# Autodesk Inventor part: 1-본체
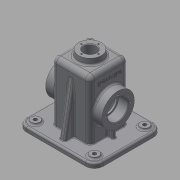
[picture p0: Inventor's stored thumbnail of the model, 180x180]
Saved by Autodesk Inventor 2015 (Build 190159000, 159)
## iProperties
Created: 2016-06
Part Number: 1-본체
Material: 일반
Document SubType Name: Modeling
Designer: aa
Density: 1 g/cm^3
Appearance: 기본값
Author: aa
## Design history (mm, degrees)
sketch "스케치1"
  geometry: L1 (65, -57.5)-(-65, -57.5); L2 (-65, -57.5)-(-65, 57.5); L3 (-65, 57.5)-(65, 57.5); L4 (65, 57.5)-(65, -57.5); L5 (65, -57.5)-(-65, 57.5); L6 (-65, -57.5)-(65, 57.5); 1 further point
  constraints: 12 end point, 2 midpoint, 2 parallel, 1 horizontal, 1 perpendicular
  dimensions: "d0" = 130 distance between parallel lines of L4 L2; "d1" = 115 distance between parallel lines of L1 L3
extrude "돌출1" new body sketch "스케치1" distance "d2" = 10; taper "d3" = 0 deg
sketch "스케치2"
  geometry: L1 (32.5, -32.5)-(-32.5, -32.5); L2 (-32.5, -32.5)-(-32.5, 32.5); L3 (-32.5, 32.5)-(32.5, 32.5); L4 (32.5, 32.5)-(32.5, -32.5); L5 (32.5, -32.5)-(-32.5, 32.5); L6 (-32.5, -32.5)-(32.5, 32.5); 1 further point
  constraints: 12 end point, 2 midpoint, 2 parallel, 1 horizontal, 1 perpendicular
  dimensions: "d4" = 65 distance between parallel lines of L4 L2; "d5" = 65 distance of L3.end L1.start (= d4)
extrude "돌출2" join sketch "스케치2" distance "d6" = 100; taper "d7" = 0 deg
sketch "스케치3"
  geometry: L1 (-57.5, 0)-(57.5, 0) reference; C1 r 27.5 at (0, 55); 1 further point
  constraints: 1 centre point, 1 vertical alignment
  dimensions: "d8" = 55 distance from line of C1.centre L1; "d9" = 55 diameter of C1
extrude "돌출3" join sketch "스케치3" stored distance "d10" = 95; taper "d11" = 0 deg
sketch "스케치4"
  geometry: C1 r 20 at (0, 0); 1 further point
  constraints: 1 centre point, 1 coincident
  dimensions: "d12" = 40 diameter of C1
extrude "돌출4" join sketch "스케치4" distance "d13" = 10; taper "d14" = 0 deg
feature "면 기울기1" dims angle "d15" = 5 deg
sketch "스케치5"
  geometry: L1 (27.5, 27.5)-(-27.5, 27.5); L2 (-27.5, 27.5)-(-27.5, -27.5); L3 (-27.5, -27.5)-(27.5, -27.5); L4 (27.5, -27.5)-(27.5, 27.5); L5 (27.5, 27.5)-(-27.5, -27.5); L6 (-27.5, 27.5)-(27.5, -27.5); 1 further point
  constraints: 12 end point, 2 midpoint, 2 parallel, 1 horizontal, 1 perpendicular
  dimensions: "d16" = 55 distance between parallel lines of L1 L3; "d17" = 55 distance between parallel lines of L4 L2 (= d16)
extrude "돌출5" cut sketch "스케치5" distance "d18" = 105; taper "d19" = 0 deg
sketch "스케치6"
  geometry: L1 (32.5, 10)-(32.5, 110) reference; L2 (32.5, 95.069)-(47.5, 10); L3 (57.5, 10)-(-57.5, 10) reference; L4 (57.5, 0)-(57.5, 10) reference; 1 further point
  constraints: 2 end point, 2 point on line
  dimensions: "d22" = 10 deg angle of L2 L4; "d23" = 10 distance from line of L4 L2.end
feature "리브1" sketch "스케치6" dims "d24" = 1, "d25" = 10, "d26" = 0, "d27" = 0, "d28" = 1, "d29" = 1
sketch "스케치7"
  geometry: L1 (42.5, 26)-(42.5, 10); L2 (27.5, 0)-(27.5, 105) reference; L3 (-65, 10)-(65, 10) reference; 1 further point
  constraints: 2 end point, 1 point on line, 1 vertical
  dimensions: "d30" = 15 distance between parallel lines of L2 L1
feature "리브2" sketch "스케치7" dims "d31" = 1, "d32" = 6, "d33" = 0, "d34" = 0, "d35" = 1, "d36" = 1
fillet "모깎기1" dims "d20" = 8
fillet "모깎기2" dims "d21" = 8
fillet "모깎기3" dims "d37" = 15
sketch "스케치8"
  geometry: C1 r 7.5 at (50, -42.5); A1 r 15 centre (50, -42.5) between (50, -57.5) and (65, -42.5) reference; 1 further point
  constraints: 1 centre point, 1 concentric
  dimensions: "d38" = 15 diameter of C1
extrude "돌출6" join sketch "스케치8" distance "d39" = 3; taper "d40" = 0 deg
hole "구멍1" diameter "d43" = 6; stored, may be unused: countersink angle "d47" = 90 deg, drill point angle "d49" = 118 deg; dims "d41" = 10, "d42" = 10, "d44" = 6, "d45" = 4, "d46" = 2, "d48" = 8
hole "구멍2" diameter "d58" = 21; stored, may be unused: countersink angle "d62" = 90 deg, drill point angle "d64" = 118 deg; dims "d56" = 10, "d57" = 10, "d59" = 6, "d60" = 4, "d61" = 2, "d63" = 8
hole "구멍3" diameter "d67" = 30; stored, may be unused: countersink angle "d71" = 90 deg, drill point angle "d73" = 0 deg; dims "d65" = 10, "d66" = 10, "d68" = 6, "d69" = 35, "d70" = 17, "d72" = 8
sketch "스케치9"
  geometry: L1 (-50, -57.5)-(50, -57.5) reference; L2 (65, -42.5)-(65, 42.5) reference; L3 (50, 57.5)-(-50, 57.5) reference; L4 (-65, 42.5)-(-65, -42.5) reference; L5 (27.5, 27.5)-(27.5, -27.5) reference; L6 (27.5, -27.5)-(-27.5, -27.5) reference; L7 (-27.5, -27.5)-(-27.5, 27.5) reference; L8 (-27.5, 27.5)-(27.5, 27.5) reference; L9 (50, -52.5)-(-50, -52.5); L10 (-60, -42.5)-(-60, 42.5); L11 (-50, 52.5)-(50, 52.5); L12 (60, 42.5)-(60, -42.5); C1 r 3 at (50, 42.5) reference; C2 r 3 at (50, -42.5) reference; C3 r 3 at (-50, 42.5) reference; C4 r 3 at (-50, -42.5) reference; A1 r 15 centre (-50, -42.5) between (-65, -42.5) and (-50, -57.5) reference; A2 r 15 centre (50, -42.5) between (50, -57.5) and (65, -42.5) reference; A3 r 15 centre (50, 42.5) between (65, 42.5) and (50, 57.5) reference; A4 r 15 centre (-50, 42.5) between (-50, 57.5) and (-65, 42.5) reference; A5 r 10 centre (-50, -42.5) between (-60, -42.5) and (-50, -52.5); A6 r 10 centre (-50, 42.5) between (-50, 52.5) and (-60, 42.5); A7 r 10 centre (50, 42.5) between (60, 42.5) and (50, 52.5); A8 r 10 centre (50, -42.5) between (50, -52.5) and (60, -42.5); 1 further point
  constraints: 8 end point, 8 point on circle, 4 centre point, 7 other
  dimensions: "d80" = 5 distance between parallel lines of L1 L9
extrude "돌출7" cut sketch "스케치9" distance "d81" = 2; taper "d82" = 0 deg
fillet "모깎기4" dims "d74" = 3
fillet "모깎기5" dims "d75" = 3
fillet "모깎기6" dims "d76" = 3
fillet "모깎기7" dims "d77" = 3
fillet "모깎기8" dims "d78" = 1
fillet "모깎기9" dims "d79" = 3
sketch "스케치10" dims "d83" = 42
  geometry: C1 r 17.5 at (0, 0) reference; 3 further points
  constraints: 2 horizontal alignment, 3 other
hole "구멍4" sketch "스케치10" at (-21, 0) diameter "d84" = 3.242; stored, may be unused: countersink angle "d88" = 90 deg, drill point angle "d90" = 118 deg; dims "d85" = 8, "d86" = 35, "d87" = 17, "d89" = 10
sketch "스케치11" dims "d94" = 29
  geometry: 3 further points
  constraints: 2 vertical alignment, 1 coincident, 2 other
hole "구멍5" sketch "스케치11" at (0, 14.5) diameter "d95" = 2.459; stored, may be unused: countersink angle "d99" = 90 deg, drill point angle "d101" = 118 deg; dims "d96" = 7, "d97" = 35, "d98" = 17, "d100" = 9
chamfer "모따기1" distance "d105" = 1; stored, may be unused: second distance "d106" = 2, angle "d107" = 45 deg
fillet "모깎기10" dims "d108" = 0.3
sketch "스케치12"
  geometry: L1 (3, -0.5)-(3, 49.5); L2 (3, 49.5)-(13, 49.5); L3 (13, 49.5)-(13, -0.5); L4 (13, -0.5)-(3, -0.5); L5 (8, -0.5)-(8, 49.5); L6 (3, 24.5)-(13, 24.5); L7 (-10.739, 4.74)-(-10.739, 44.26) reference; L8 (-18, 43.625)-(-18, 5.375) reference; 1 further point
  constraints: 4 end point, 4 midpoint, 1 perpendicular, 1 point on line, 2 other
  dimensions: "d109" = 50 distance between parallel lines of L2 L4; "d110" = 10 distance between parallel lines of L3 L1; "d111" = 26 distance between parallel lines of L8 L5
feature "엠보싱1" sketch "스케치12" dims "d112" = 0.5, "d113" = 0
node "솔리드1"
mirror "대칭1"
mirror "대칭2"
pattern_linear "직사각형 패턴1" dims "d52" = 85
mirror "대칭3"
pattern_circular "원형 패턴1" dims angle "d92" = 360 deg
mirror "대칭4"
pattern_circular "원형 패턴2" dims angle "d103" = 360 deg
node "투영된 루프1"
